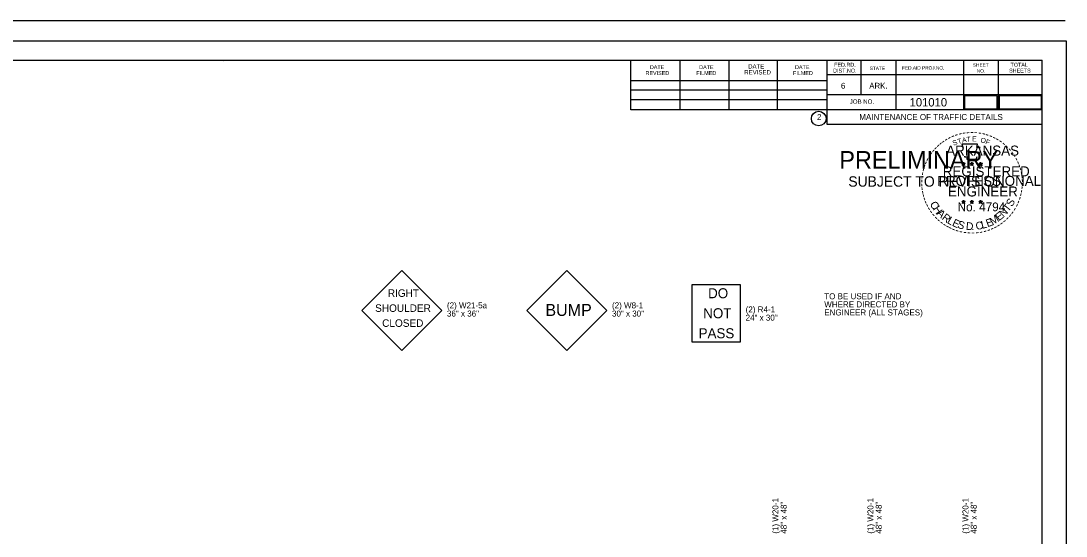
# Model space of a CAD drawing. Extents: x 6125 to 14104, y 8730 to 11067.
# Drawn here: x 6841 to 7886, y 10551 to 11067 of the extents above; entities that cross this region are included whole.
import ezdxf

# ---------------------------------------------------------------- set-up
doc = ezdxf.new("R2010")
doc.units = 0
for name, color, linetype in [('C-PSVP', 7, 'Continuous'), ('GREEN_TXT', 7, 'Continuous'), ('R_Border Notes', 7, 'Continuous'), ('R_Proposed Road', 7, 'Continuous'), ('SEAL-INFO', 7, 'Continuous'), ('SIGNATURE', 7, 'Continuous'), ('Stage 1', 7, 'Continuous'), ('Stage 1 Construction', 7, 'Continuous'), ('Stage 3', 7, 'Continuous')]:
    doc.layers.add(name, color=color, linetype=linetype)

msp = doc.modelspace()

# ---------------------------------------------------------------- linework, layer by layer
msp.add_lwpolyline([(7387.2, 10817), (7427.2, 10777), (7387.2, 10737), (7347.2, 10777)], close=True)
at = {"layer": 'C-PSVP'}
for p, q in [((7781.8, 10924), (7783.6, 10923.5)), ((7781.8, 10924), (7783.1, 10923.8)), ((7781.8, 10924), (7783, 10923.4)), ((7782.5, 10922), (7783.6, 10923.5)), ((7782.5, 10922), (7783.1, 10923.2)), ((7782.5, 10922), (7783.6, 10923.1)), ((7783.6, 10925.3), (7783.4, 10924.1)), ((7783.6, 10923.5), (7783.6, 10925.3)), ((7783.6, 10925.3), (7783.8, 10924.1)), ((7785.3, 10924), (7783.6, 10923.5)), ((7784.6, 10922), (7783.6, 10923.5)), ((7784.6, 10922), (7783.6, 10923.1)), ((7785.3, 10924), (7783.9, 10923.8)), ((7784.6, 10922), (7784, 10923.5)), ((7785.3, 10924), (7784.3, 10923.5)), ((7790.2, 10924), (7791.9, 10923.5)), ((7790.2, 10924), (7791.4, 10923.8)), ((7790.2, 10924), (7791.4, 10923.4)), ((7790.8, 10922), (7791.9, 10923.5)), ((7790.8, 10922), (7791.5, 10923.2)), ((7790.8, 10922), (7791.9, 10923.1)), ((7791.9, 10925.3), (7791.7, 10924.1)), ((7791.9, 10923.5), (7791.9, 10925.3)), ((7791.9, 10925.3), (7792.2, 10924.1)), ((7793.7, 10924), (7791.9, 10923.5)), ((7793, 10922), (7791.9, 10923.5)), ((7793, 10922), (7791.9, 10923.1)), ((7793.7, 10924), (7792.2, 10923.8)), ((7793, 10922), (7792.3, 10923.5)), ((7793.7, 10924), (7792.6, 10923.5)), ((7799, 10924), (7800.7, 10923.4)), ((7799, 10924), (7800.3, 10923.8)), ((7799, 10924), (7800.2, 10923.4)), ((7799.7, 10921.9), (7800.7, 10923.4)), ((7799.7, 10921.9), (7800.3, 10923.2)), ((7799.7, 10921.9), (7800.7, 10923)), ((7800.7, 10925.3), (7800.5, 10924)), ((7800.7, 10923.4), (7800.7, 10925.3)), ((7800.7, 10925.3), (7801, 10924)), ((7802.5, 10924), (7800.7, 10923.4)), ((7801.8, 10921.9), (7800.7, 10923.4)), ((7801.8, 10921.9), (7800.7, 10923)), ((7802.5, 10924), (7801.1, 10923.7)), ((7801.8, 10921.9), (7801.1, 10923.4)), ((7802.5, 10924), (7801.5, 10923.5)), ((7781.8, 10886.2), (7783.6, 10885.6)), ((7781.8, 10886.2), (7783.1, 10886)), ((7781.8, 10886.2), (7783, 10885.6)), ((7782.5, 10884.1), (7783.6, 10885.6)), ((7782.5, 10884.1), (7783.1, 10885.4)), ((7782.5, 10884.1), (7783.5, 10885.2)), ((7783.6, 10887.4), (7783.4, 10886.2)), ((7784.6, 10884.1), (7783.5, 10885.2)), ((7783.6, 10885.6), (7783.6, 10887.4)), ((7783.6, 10887.4), (7783.8, 10886.2)), ((7785.3, 10886.2), (7783.6, 10885.6)), ((7784.6, 10884.1), (7783.6, 10885.6)), ((7785.3, 10886.2), (7783.9, 10885.9)), ((7784.6, 10884.1), (7783.9, 10885.6)), ((7785.3, 10886.2), (7784.3, 10885.7)), ((7790.2, 10886.2), (7791.9, 10885.6)), ((7790.2, 10886.2), (7791.4, 10886)), ((7790.2, 10886.2), (7791.3, 10885.6)), ((7790.8, 10884.1), (7791.9, 10885.6)), ((7790.8, 10884.1), (7791.5, 10885.4)), ((7790.8, 10884.1), (7791.9, 10885.2)), ((7791.9, 10887.4), (7791.7, 10886.2)), ((7791.9, 10885.6), (7791.9, 10887.4)), ((7791.9, 10887.4), (7792.1, 10886.2)), ((7793.6, 10886.2), (7791.9, 10885.6)), ((7793, 10884.1), (7791.9, 10885.6)), ((7793, 10884.1), (7791.9, 10885.2)), ((7793.6, 10886.2), (7792.2, 10885.9)), ((7793, 10884.1), (7792.3, 10885.6)), ((7793.6, 10886.2), (7792.6, 10885.7)), ((7799, 10886.1), (7800.7, 10885.6)), ((7799, 10886.1), (7800.3, 10885.9)), ((7799, 10886.1), (7800.2, 10885.5)), ((7799.7, 10884.1), (7800.7, 10885.6)), ((7799.7, 10884.1), (7800.3, 10885.3)), ((7799.7, 10884.1), (7800.7, 10885.2)), ((7800.7, 10887.4), (7800.5, 10886.1)), ((7800.7, 10885.6), (7800.7, 10887.4)), ((7800.7, 10887.4), (7801, 10886.1)), ((7802.5, 10886.1), (7800.7, 10885.6)), ((7801.8, 10884.1), (7800.7, 10885.6)), ((7801.8, 10884.1), (7800.7, 10885.2)), ((7802.5, 10886.1), (7801, 10885.9)), ((7801.8, 10884.1), (7801.1, 10885.5)), ((7802.5, 10886.1), (7801.5, 10885.6))]:
    msp.add_line(p, q, dxfattribs=at)
for points in [[(7782, 10943.4), (7783.4, 10939.3)], [(7799.6, 10938.8), (7800.3, 10940.2), (7796.9, 10940.1), (7797.6, 10943.4), (7782, 10943.4)], [(7784.5, 10931.3), (7784.5, 10930.9), (7787.3, 10930.8), (7787, 10928.4), (7796.4, 10928.4), (7797.4, 10931.1)], [(7783.6, 10925.3), (7784.6, 10922), (7781.8, 10924), (7785.3, 10924), (7782.5, 10922), (7783.6, 10925.3)], [(7791.9, 10925.3), (7793, 10922), (7790.2, 10924), (7793.7, 10924), (7790.8, 10922), (7791.9, 10925.3)], [(7800.7, 10925.3), (7801.8, 10921.9), (7799, 10924), (7802.5, 10924), (7799.7, 10921.9), (7800.7, 10925.3)], [(7783.6, 10887.4), (7784.6, 10884.1), (7781.8, 10886.2), (7785.3, 10886.2), (7782.5, 10884.1), (7783.6, 10887.4)], [(7791.9, 10887.4), (7793, 10884.1), (7790.2, 10886.2), (7793.6, 10886.2), (7790.8, 10884.1), (7791.9, 10887.4)], [(7800.7, 10887.4), (7801.8, 10884.1), (7799, 10886.1), (7802.5, 10886.1), (7799.7, 10884.1), (7800.7, 10887.4)]]:
    msp.add_lwpolyline(points, dxfattribs=at)
for centre, radius in [((7783.6, 10923.5), 0.861), ((7783.6, 10923.5), 0.723), ((7783.6, 10923.5), 0.579), ((7783.6, 10923.5), 0.495), ((7783.6, 10923.5), 0.374), ((7783.6, 10923.5), 0.248), ((7783.6, 10923.5), 0.148), ((7791.9, 10923.5), 0.861), ((7791.9, 10923.5), 0.723), ((7791.9, 10923.5), 0.579), ((7791.9, 10923.5), 0.495), ((7791.9, 10923.5), 0.374), ((7791.9, 10923.5), 0.248), ((7791.9, 10923.5), 0.148), ((7800.7, 10923.4), 0.861), ((7800.7, 10923.4), 0.723), ((7800.7, 10923.4), 0.579), ((7800.7, 10923.4), 0.495), ((7800.7, 10923.4), 0.374), ((7800.7, 10923.4), 0.248), ((7800.7, 10923.4), 0.148), ((7783.5, 10885.6), 0.861), ((7783.5, 10885.6), 0.723), ((7783.5, 10885.6), 0.579), ((7783.5, 10885.6), 0.495), ((7783.5, 10885.6), 0.374), ((7783.5, 10885.6), 0.248), ((7783.5, 10885.6), 0.148), ((7791.9, 10885.6), 0.861), ((7791.9, 10885.6), 0.723), ((7791.9, 10885.6), 0.579), ((7791.9, 10885.6), 0.495), ((7791.9, 10885.6), 0.374), ((7791.9, 10885.6), 0.248), ((7791.9, 10885.6), 0.148), ((7800.7, 10885.6), 0.861), ((7800.7, 10885.6), 0.723), ((7800.7, 10885.6), 0.579), ((7800.7, 10885.6), 0.495), ((7800.7, 10885.6), 0.374), ((7800.7, 10885.6), 0.248), ((7800.7, 10885.6), 0.148)]:
    msp.add_circle(centre, radius, dxfattribs=at)
at = {"layer": 'GREEN_TXT'}
for p, q in [((7885.4, 11066.7), (6125.4, 11066.7)), ((6281.5, 11027.3), (7862.4, 11027.3)), ((7044.1, 11026), (7044.1, 11026)), ((7044.1, 11026), (7044.1, 11026)), ((7451.1, 10977.9), (7451.1, 11027.3)), ((7500.4, 10977.9), (7500.4, 11026.3)), ((7549.2, 10977.9), (7549.2, 11026.3)), ((7597.6, 10977.9), (7597.6, 11026.3)), ((7646.9, 11027.3), (7646.9, 10963.3)), ((7681.1, 11027.3), (7681.1, 10992.6)), ((7715.8, 11027.3), (7715.8, 10977.9)), ((7783.7, 11027.3), (7783.7, 10977.9)), ((7818.4, 11027.3), (7818.4, 10977.9)), ((7862.4, 10000), (7862.4, 11027.3)), ((7451.1, 11007.2), (7646.9, 11007.2)), ((7862.4, 11012.6), (7646.9, 11012.6)), ((7862.4, 11012.7), (7862.4, 11012.7)), ((7451.1, 10997.9), (7646.9, 10997.9)), ((7451.1, 10988.2), (7646.9, 10988.2)), ((7862.4, 10992.6), (7646.9, 10992.6)), ((7862.4, 10977.9), (7451.1, 10977.9)), ((7646.9, 10963.3), (7862.4, 10963.3))]:
    msp.add_line(p, q, dxfattribs=at)
msp.add_circle((7638.9, 10969), 7.33, dxfattribs=at)
at = {"layer": 'R_Proposed Road'}
msp.add_lwpolyline([(7784.7, 10978.6), (7817.4, 10978.6), (7817.4, 10991.9), (7784.7, 10991.9)], close=True, dxfattribs=at)
at = {"layer": 'SEAL-INFO'}
msp.add_lwpolyline([(6219.5, 11046.8), (7886.2, 11046.8), (7886.2, 9980.1), (6219.5, 9980.1)], close=True, dxfattribs=at)
at = {"layer": 'Stage 1'}
for points in [[(7222.2, 10817), (7262.2, 10777), (7222.2, 10737), (7182.2, 10777)], [(7512.2, 10802.9), (7560.3, 10802.9), (7560.3, 10745.3), (7512.2, 10745.3)]]:
    msp.add_lwpolyline(points, close=True, dxfattribs=at)
at = {"layer": 'Stage 3'}
msp.add_lwpolyline([(7819.2, 10978.6), (7861.6, 10978.6), (7861.6, 10991.9), (7819.2, 10991.9)], close=True, dxfattribs=at)

# ---------------------------------------------------------------- texts
for s, height, rotation, p in [('DO', 10, 360, (7528.3, 10789.3)), ('(2) W8-1', 6, 360, (7432.2, 10779.2)), ('BUMP', 12, 360, (7365.6, 10771.6)), ('30" x 30"', 6, 360, (7432.2, 10771)), ('NOT', 10, 360, (7523.4, 10769.3)), ('PASS', 10, 360, (7518.8, 10749.3)), ('(1) W20-1', 6, 90, (7598.6, 10553.8)), ('48" x 48"', 6, 90, (7606.9, 10553.8)), ('(1) W20-1', 6, 90, (7693.6, 10553.8)), ('48" x 48"', 6, 90, (7701.9, 10553.8)), ('(1) W20-1', 6, 90, (7788.6, 10553.8)), ('48" x 48"', 6, 90, (7796.9, 10553.8))]:
    msp.add_text(s, height=height, rotation=rotation).set_placement(p)
at = {"layer": 'C-PSVP'}
for s, height, rotation, p in [('-', 8, 24.3072, (7772.6, 10947.7)), ('-', 8, 19.1761, (7775.8, 10949.1)), ('-', 8, 13.6302, (7779.5, 10950.3)), ('-', 8, 10.2193, (7782.9, 10951.1)), ('T', 5, 6.0228, (7786.8, 10945.6)), ('-', 8, 5.8968, (7786.6, 10951.6)), ('-', 8, 0.1862, (7790.4, 10952)), ('E', 5, 0.8323, (7792.3, 10946.1)), ('-', 8, 357.743, (7794, 10951.9)), ('-', 8, 352.1617, (7797.8, 10951.6)), ('-', 8, 347.2049, (7801.4, 10951.1)), ('-', 8, 342.3362, (7804.5, 10950.3)), ('-', 8, 337.8551, (7808.2, 10949.2)), ('-', 8, 48.4231, (7756.8, 10935.9)), ('-', 8, 42.9622, (7759, 10938.3)), ('-', 8, 38.9507, (7761.2, 10940.4)), ('-', 8, 36.2317, (7763.6, 10942.3)), ('-', 8, 34.0636, (7766.5, 10944.3)), ('-', 8, 28.7918, (7769.4, 10946.1)), ('S', 5, 21.594, (7773.8, 10941.8)), ('T', 5, 16.4036, (7778.4, 10943.5)), ('A', 5, 11.2132, (7782.5, 10944.7)), ('O', 5, 350.4515, (7800.3, 10945.1)), ('F', 5, 340.0707, (7805.1, 10943.9)), ('-', 8, 334.1211, (7811.4, 10947.8)), ('-', 8, 329.6409, (7814.3, 10946.4)), ('-', 8, 325.8627, (7817.5, 10944.6)), ('-', 8, 320.5297, (7820.5, 10942.5)), ('-', 8, 315.5786, (7823.5, 10940)), ('-', 8, 58.0706, (7751.1, 10928)), ('-', 8, 54.2325, (7752.7, 10930.7)), ('-', 8, 50.6142, (7754.8, 10933.5)), ('-', 8, 309.8797, (7826.4, 10937.3)), ('-', 8, 306.6522, (7829, 10934.3)), ('-', 7, 303.6753, (7831.4, 10931.4)), ('-', 8, 72.3945, (7747.1, 10918.8)), ('-', 8, 67.7743, (7748.2, 10921.9)), ('-', 8, 62.8713, (7749.5, 10925)), ('-', 8, 299.6684, (7833, 10928.4)), ('-', 8, 294.6628, (7834.6, 10925.3)), ('-', 8, 290.5728, (7835.9, 10922.5)), ('-', 8, 285.1233, (7837.1, 10919.6)), ('-', 8, 85.1863, (7745.1, 10908.2)), ('-', 8, 81.2013, (7745.5, 10911.6)), ('-', 8, 75.461, (7746.1, 10915.2)), ('-', 8, 280.5493, (7838.1, 10915.9)), ('-', 8, 276.5962, (7838.9, 10912)), ('-', 8, 89.0622, (7745, 10904.7)), ('-', 8, 94.1959, (7745.1, 10901.1)), ('-', 8, 98.9479, (7745.5, 10897.7)), ('-', 8, 263.5172, (7839.3, 10901.9)), ('-', 8, 274.3301, (7839.2, 10908.4)), ('-', 8, 269.9407, (7839.4, 10905.2)), ('-', 8, 101.7149, (7746.2, 10894.1)), ('-', 8, 105.4578, (7747, 10891.1)), ('-', 8, 109.0874, (7748.1, 10887.9)), ('S', 7.7, 57.878, (7832, 10880.3)), ('-', 8, 255.7626, (7837.4, 10891.8)), ('-', 8, 255.7626, (7838.4, 10895.3)), ('-', 8, 260.9953, (7838.9, 10898.6)), ('-', 8, 114.0643, (7749.3, 10884.9)), ('-', 8, 115.7289, (7750.9, 10881.9)), ('-', 8, 120.4471, (7752.6, 10878.9)), ('C', 7.7, 296.9133, (7749.7, 10883.9)), ('H', 7.7, 303.2799, (7752.7, 10878.7)), ('N', 7.7, 45.1449, (7823.6, 10869.9)), ('T', 7.7, 51.5114, (7828.4, 10875.1)), ('-', 8, 239.0712, (7833.1, 10881.4)), ('-', 8, 244.6197, (7835, 10885.1)), ('-', 8, 247.8887, (7836.3, 10888.3)), ('-', 8, 125.8934, (7754.7, 10876.1)), ('-', 8, 130.7181, (7757, 10873.4)), ('-', 8, 134.2238, (7759.6, 10870.6)), ('A', 7.7, 316.013, (7756.3, 10873.6)), ('-', 8, 138.9338, (7762.2, 10868.3)), ('R', 7.7, 322.3796, (7761.4, 10868.7)), ('L', 7.7, 328.7461, (7766.6, 10864.9)), ('E', 7.7, 335.1127, (7771.6, 10862.1)), ('E', 7.7, 19.6786, (7807.6, 10860.3)), ('M', 7.7, 32.4117, (7812.7, 10862.1)), ('E', 7.7, 38.7783, (7819.1, 10866.2)), ('-', 8, 221.0851, (7823.9, 10869.9)), ('-', 8, 225.7653, (7826.5, 10872.5)), ('-', 8, 231.2538, (7828.9, 10875.3)), ('-', 8, 233.8452, (7831.1, 10878.1)), ('-', 8, 144.6463, (7765, 10866.3)), ('-', 8, 148.0898, (7767.8, 10864.4)), ('-', 8, 151.5704, (7770.7, 10862.8)), ('-', 8, 154.6002, (7773.3, 10861.6)), ('-', 8, 158.5612, (7776.4, 10860.3)), ('-', 8, 162.7983, (7779.8, 10859.2)), ('S', 7.7, 341.4792, (7776.9, 10860)), ('D', 7.7, 354.2124, (7785.7, 10857.9)), ('.', 7.7, 0.5789, (7791.6, 10857.5)), ('C', 7.7, 6.9455, (7796.2, 10857.7)), ('L', 7.7, 13.3121, (7802.1, 10858.7)), ('-', 8, 195.4743, (7806.1, 10859.7)), ('-', 8, 200.7184, (7809.5, 10860.9)), ('-', 8, 204.2516, (7812.6, 10862.3)), ('-', 8, 207.3568, (7815.7, 10863.9)), ('-', 8, 212.2491, (7818.5, 10865.6)), ('-', 8, 215.7363, (7821.2, 10867.6)), ('-', 8, 167.5555, (7783.4, 10858.4)), ('-', 8, 173.1155, (7787.3, 10857.9)), ('-', 8, 176.5183, (7791, 10857.6)), ('-', 8, 181.5918, (7794.7, 10857.7)), ('-', 8, 185.8167, (7798.8, 10858.1)), ('-', 8, 191.2858, (7802.4, 10858.7))]:
    msp.add_text(s, height=height, rotation=rotation, dxfattribs=at).set_placement(p)
for s, height, p in [('ARKANSAS', 10, (7766.3, 10932)), ('REGISTERED', 10, (7762.9, 10911.2)), ('PROFESSIONAL', 10, (7757.2, 10901.7)), ('ENGINEER', 10, (7768.1, 10891.1)), ('No. 4794', 8.78, (7777.7, 10876.3))]:
    msp.add_text(s, height=height, dxfattribs=at).set_placement(p)
at = {"layer": 'GREEN_TXT'}
for s, height, p in [('FED.RD.', 3.91, (7654.3, 11020.9)), ('SHEET', 3.42, (7793, 11020.9)), ('TOTAL', 3.91, (7830.6, 11020.9)), ('REVISED', 3.91, (7465.7, 11012.6)), ('DATE', 3.91, (7470.1, 11018.5)), ('FILMED', 3.91, (7516.5, 11012.6)), ('DATE', 3.91, (7519.4, 11018.5)), ('REVISED', 4.4, (7564.4, 11013.1)), ('DATE', 4.4, (7568.3, 11019)), ('FILMED', 3.91, (7613.2, 11012.6)), ('DATE', 3.91, (7615.2, 11018.5)), ('DIST.NO.', 3.91, (7653.3, 11015)), ('STATE', 3.42, (7689.9, 11017.5)), ('FED.AID PROJ.NO.', 3.42, (7722.2, 11018)), ('NO.', 3.42, (7796.9, 11015)), ('SHEETS', 3.91, (7829.2, 11015)), ('6', 5.86, (7661.1, 10998.9)), ('ARK.', 5.86, (7689.4, 10998.9)), ('JOB NO.', 4.4, (7669.9, 10983.8)), ('2', 5.86, (7637.2, 10967.7))]:
    msp.add_text(s, height=height, dxfattribs=at).set_placement(p)
at = {"layer": 'R_Border Notes'}
for s, height, p in [('101010', 8.4, (7729.7, 10981.1)), ('MAINTENANCE OF TRAFFIC DETAILS', 6, (7679.4, 10967.6))]:
    msp.add_text(s, height=height, dxfattribs=at).set_placement(p)
at = {"layer": 'SIGNATURE'}
for s, height, p in [('PRELIMINARY', 17.5, (7659.5, 10919)), ('SUBJECT TO REVISION', 10.376, (7668.5, 10900.9))]:
    msp.add_text(s, height=height, dxfattribs=at).set_placement(p)
at = {"layer": 'Stage 1'}
for s, height, p in [('RIGHT', 7.5, (7208.1, 10790.7)), ('(2) W21-5a', 6, (7267.2, 10779.2)), ('SHOULDER', 7.5, (7195.4, 10775.7)), ('36" x 36"', 6, (7267.2, 10771)), ('(2) R4-1', 6, (7565.8, 10775.1)), ('CLOSED', 7.5, (7202.4, 10760.7)), ('24" x 30"', 6, (7565.8, 10766.9))]:
    msp.add_text(s, height=height, rotation=360, dxfattribs=at).set_placement(p)
at = {"layer": 'Stage 1 Construction'}
for s, p in [('TO BE USED IF AND', (7644.4, 10788.3)), ('WHERE DIRECTED BY', (7644.4, 10780.2)), ('ENGINEER (ALL STAGES)', (7644.4, 10772.1))]:
    msp.add_text(s, height=6, dxfattribs=at).set_placement(p)

doc.saveas('drawing.dxf')
